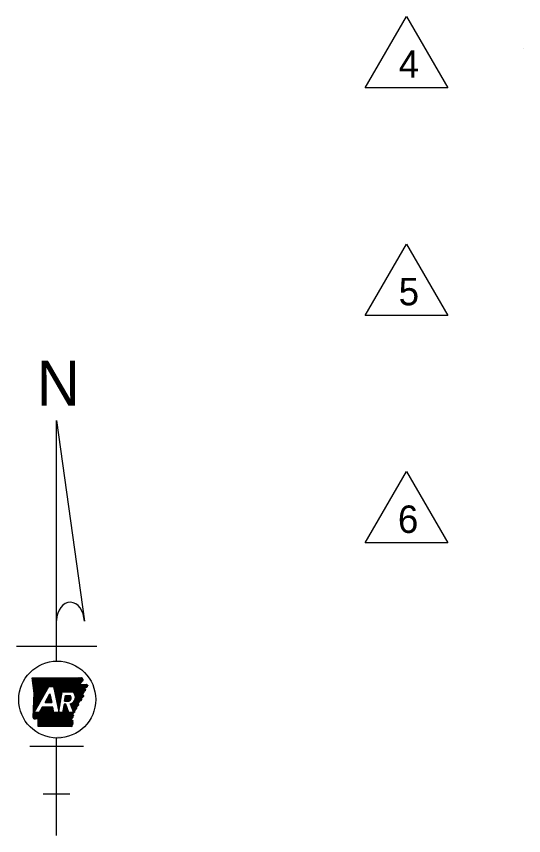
# Model space of a CAD drawing. Extents: x -33639 to 34530, y -17264 to 5867.
# Drawn here: x -7282 to -5621, y -15354 to -12669 of the extents above; entities that cross this region are included whole.
import ezdxf

# ---------------------------------------------------------------- set-up
doc = ezdxf.new("R2010")
doc.units = 0
doc.layers.add('R_Annotation', color=7, linetype='Continuous')
doc.layers.add('S_MISC_BOUNDARY', color=7, linetype='Continuous')

msp = doc.modelspace()

# ---------------------------------------------------------------- linework, layer by layer
at = {"layer": 'R_Annotation'}
for p, q in [((-7150.3, -13993.8), (-7059.3, -14650.9)), ((-7150.3, -14781.8), (-7150.3, -13993.8)), ((-7281.9, -14733), (-7018.7, -14733)), ((-7230.1, -14838.2), (-7229, -14837.1)), ((-7229.7, -14841.3), (-7225.5, -14837.1)), ((-7229.3, -14844.4), (-7222, -14837.1)), ((-7228.9, -14847.5), (-7218.6, -14837.1)), ((-7228.5, -14850.6), (-7215.1, -14837.1)), ((-7228.2, -14853.7), (-7211.6, -14837.1)), ((-7227.8, -14856.8), (-7208.1, -14837.1)), ((-7227.4, -14859.9), (-7204.6, -14837.1)), ((-7227, -14863), (-7201.2, -14837.1)), ((-7226.6, -14866.1), (-7197.7, -14837.1)), ((-7226.2, -14869.2), (-7194.2, -14837.1)), ((-7225.8, -14872.3), (-7190.7, -14837.1)), ((-7225.5, -14875.4), (-7187.2, -14837.1)), ((-7225.1, -14878.5), (-7183.8, -14837.1)), ((-7225, -14913.2), (-7148.9, -14837.1)), ((-7224.8, -14909.6), (-7152.3, -14837.1)), ((-7224.7, -14906), (-7155.8, -14837.1)), ((-7224.7, -14881.6), (-7180.3, -14837.1)), ((-7224.6, -14902.4), (-7159.3, -14837.1)), ((-7224.5, -14898.8), (-7162.8, -14837.1)), ((-7224.4, -14895.2), (-7166.3, -14837.1)), ((-7224.3, -14884.7), (-7176.8, -14837.1)), ((-7224.2, -14891.6), (-7169.8, -14837.1)), ((-7224.1, -14888), (-7173.3, -14837.1)), ((-7173.2, -14864.9), (-7145.4, -14837.1)), ((-7169.8, -14864.9), (-7141.9, -14837.1)), ((-7166.3, -14864.9), (-7138.4, -14837)), ((-7162.8, -14864.9), (-7134.8, -14837)), ((-7160.6, -14866.3), (-7131.3, -14836.9)), ((-7160, -14869.1), (-7127.8, -14836.9)), ((-7159.4, -14872), (-7124.2, -14836.8)), ((-7158.8, -14874.9), (-7120.7, -14836.8)), ((-7158.2, -14877.7), (-7117.1, -14836.7)), ((-7157.6, -14880.6), (-7113.6, -14836.6)), ((-7156.9, -14883.5), (-7110.1, -14836.6)), ((-7156.3, -14886.3), (-7106.5, -14836.5)), ((-7155.7, -14889.2), (-7103, -14836.5)), ((-7155.1, -14892.1), (-7099.4, -14836.4)), ((-7154.5, -14894.9), (-7095.9, -14836.4)), ((-7153.9, -14897.8), (-7092.4, -14836.3)), ((-7153.3, -14900.7), (-7088.8, -14836.2)), ((-7152.6, -14903.5), (-7085.3, -14836.2)), ((-7128.4, -14882.8), (-7081.7, -14836.1)), ((-7125, -14882.8), (-7078.1, -14836)), ((-7121.5, -14882.8), (-7074.6, -14835.9)), ((-7118, -14882.8), (-7071, -14835.8)), ((-7114.5, -14882.8), (-7067.4, -14835.8)), ((-7111, -14882.8), (-7066.7, -14838.5)), ((-7107.5, -14882.8), (-7065, -14840.3)), ((-7104.1, -14882.8), (-7064.5, -14843.3)), ((-7225.1, -14916.8), (-7178.1, -14869.8)), ((-7223.9, -14950.7), (-7175.3, -14864.9)), ((-7175.3, -14864.9), (-7160.9, -14864.9)), ((-7100.6, -14882.8), (-7072.5, -14854.7)), ((-7097.4, -14883.2), (-7073.2, -14858.9)), ((-7095.5, -14884.7), (-7069.5, -14858.7)), ((-7093.8, -14886.5), (-7065.8, -14858.5)), ((-7092.3, -14888.5), (-7062.1, -14858.3)), ((-7091, -14890.7), (-7058.5, -14858.1)), ((-7090, -14893.1), (-7054.8, -14857.9)), ((-7089.2, -14895.8), (-7051.5, -14858.1)), ((-7088.7, -14898.8), (-7049.9, -14860)), ((-7088.7, -14902.3), (-7058.2, -14871.8)), ((-7051.4, -14865), (-7048.2, -14861.8)), ((-7225.4, -14927.6), (-7191.7, -14893.9)), ((-7225.3, -14924), (-7187.2, -14885.8)), ((-7225.2, -14920.4), (-7182.6, -14877.8)), ((-7188.2, -14917.1), (-7172.3, -14889)), ((-7183.9, -14909.4), (-7170.7, -14896.3)), ((-7179.3, -14901.4), (-7171.3, -14893.4)), ((-7174.8, -14893.4), (-7172, -14890.6)), ((-7152, -14906.4), (-7132.3, -14886.7)), ((-7151.4, -14909.3), (-7133, -14890.9)), ((-7150.8, -14912.2), (-7133.7, -14895.1)), ((-7131.6, -14882.8), (-7097.9, -14882.8)), ((-7124.3, -14913.3), (-7105.9, -14894.9)), ((-7123.5, -14909.1), (-7109.4, -14894.9)), ((-7122.8, -14904.9), (-7112.9, -14894.9)), ((-7122.1, -14900.6), (-7116.4, -14894.9)), ((-7121.3, -14896.4), (-7119.9, -14894.9)), ((-7121.1, -14894.9), (-7105.2, -14894.9)), ((-7120.8, -14913.3), (-7104, -14896.5)), ((-7103.8, -14927.8), (-7065.2, -14889.2)), ((-7102.8, -14930.4), (-7064.5, -14892)), ((-7101.9, -14932.9), (-7063.9, -14894.9)), ((-7101, -14935.4), (-7063.2, -14897.7)), ((-7092.4, -14913), (-7065.8, -14886.4)), ((-7089.4, -14906.5), (-7057.8, -14874.9)), ((-7061.7, -14882.2), (-7057.4, -14877.9)), ((-7225.8, -14938.4), (-7205.4, -14918)), ((-7225.7, -14934.8), (-7200.8, -14909.9)), ((-7225.6, -14931.2), (-7196.3, -14901.9)), ((-7188.2, -14917.1), (-7166.3, -14917.1)), ((-7188, -14917.1), (-7170.1, -14899.2)), ((-7184.5, -14917.1), (-7169.5, -14902)), ((-7181.1, -14917.1), (-7168.9, -14904.9)), ((-7177.6, -14917.1), (-7168.3, -14907.8)), ((-7174.1, -14917.1), (-7167.7, -14910.6)), ((-7170.6, -14917.1), (-7167, -14913.5)), ((-7167.1, -14917.1), (-7166.4, -14916.4)), ((-7150.2, -14915), (-7134.5, -14899.3)), ((-7149.6, -14917.9), (-7135.2, -14903.5)), ((-7149, -14920.8), (-7135.9, -14907.7)), ((-7148.3, -14923.6), (-7136.7, -14912)), ((-7147.7, -14926.5), (-7137.4, -14916.2)), ((-7147.1, -14929.4), (-7138.1, -14920.4)), ((-7146.5, -14932.2), (-7138.9, -14924.6)), ((-7127.3, -14930.4), (-7120.3, -14923.4)), ((-7126.5, -14926.2), (-7123.8, -14923.4)), ((-7120.2, -14923.4), (-7126, -14923.4)), ((-7124.3, -14913.3), (-7109.8, -14913.3)), ((-7110.1, -14950.7), (-7120.2, -14923.4)), ((-7117.3, -14913.3), (-7102.8, -14898.8)), ((-7113.8, -14913.3), (-7102.2, -14901.6)), ((-7110.3, -14913.3), (-7102.5, -14905.4)), ((-7105.9, -14922), (-7095.3, -14950.7)), ((-7105.6, -14922.7), (-7104.6, -14921.7)), ((-7104.7, -14925.3), (-7098.1, -14918.6)), ((-7100, -14938), (-7079.1, -14917.1)), ((-7099.1, -14940.5), (-7079.5, -14921)), ((-7098.1, -14943.1), (-7079.9, -14924.8)), ((-7075.1, -14913.1), (-7070.2, -14908.2)), ((-7226.7, -14967.2), (-7210.3, -14950.7)), ((-7226.6, -14963.6), (-7213.8, -14950.7)), ((-7226.5, -14960), (-7217.2, -14950.7)), ((-7226.4, -14956.4), (-7220.7, -14950.7)), ((-7226.3, -14952.8), (-7223.6, -14950.1)), ((-7226.2, -14949.2), (-7219, -14942)), ((-7226, -14945.6), (-7214.5, -14934)), ((-7225.9, -14942), (-7209.9, -14926)), ((-7225.4, -14969.3), (-7188.8, -14932.7)), ((-7207.3, -14950.7), (-7223.9, -14950.7)), ((-7223.3, -14970.8), (-7185.3, -14932.7)), ((-7220.8, -14971.7), (-7181.8, -14932.7)), ((-7216.7, -14971.1), (-7178.3, -14932.7)), ((-7213.2, -14971), (-7174.9, -14932.7)), ((-7210.4, -14971.8), (-7171.4, -14932.7)), ((-7210.3, -14978.6), (-7164.4, -14932.7)), ((-7210.3, -14975.1), (-7167.9, -14932.7)), ((-7210.3, -14982.1), (-7162.6, -14934.4)), ((-7210.3, -14985.6), (-7162, -14937.3)), ((-7210.3, -14989), (-7161.4, -14940.1)), ((-7210.3, -14992.5), (-7160.7, -14943)), ((-7210.2, -14995.9), (-7160.1, -14945.9)), ((-7197.1, -14932.7), (-7207.3, -14950.7)), ((-7206.7, -14995.9), (-7159.5, -14948.7)), ((-7203.3, -14943.8), (-7192.3, -14932.7)), ((-7203.3, -14996), (-7158, -14950.7)), ((-7199.8, -14996), (-7154.6, -14950.7)), ((-7198.8, -14935.7), (-7195.8, -14932.7)), ((-7162.9, -14932.7), (-7197.1, -14932.7)), ((-7196.3, -14996), (-7151.1, -14950.7)), ((-7192.8, -14996), (-7147.6, -14950.7)), ((-7189.3, -14996), (-7144.1, -14950.7)), ((-7185.9, -14996), (-7140.6, -14950.7)), ((-7182.4, -14996), (-7137.1, -14950.7)), ((-7178.9, -14996), (-7133.7, -14950.7)), ((-7175.4, -14996), (-7115.5, -14936.1)), ((-7172, -14996), (-7114.6, -14938.6)), ((-7168.5, -14996), (-7113.7, -14941.2)), ((-7165, -14996), (-7112.7, -14943.7)), ((-7161.5, -14996), (-7111.8, -14946.3)), ((-7130.8, -14950.7), (-7159.1, -14950.7)), ((-7158, -14996), (-7110.8, -14948.8)), ((-7154.6, -14996), (-7109.3, -14950.7)), ((-7151.1, -14996), (-7105.8, -14950.7)), ((-7147.6, -14996), (-7102.3, -14950.7)), ((-7145.9, -14935.1), (-7139.6, -14928.8)), ((-7145.3, -14938), (-7140.3, -14933)), ((-7144.7, -14940.8), (-7141.1, -14937.3)), ((-7144.1, -14996), (-7098.8, -14950.7)), ((-7144, -14943.7), (-7141.8, -14941.5)), ((-7143.4, -14946.6), (-7142.6, -14945.7)), ((-7130.2, -14947.3), (-7116.5, -14933.6)), ((-7129.5, -14943.1), (-7117.4, -14931)), ((-7128.7, -14938.8), (-7118.4, -14928.5)), ((-7128, -14934.6), (-7119.3, -14925.9)), ((-7095.3, -14950.7), (-7110.1, -14950.7)), ((-7097.2, -14945.6), (-7086.5, -14934.9)), ((-7096.3, -14948.2), (-7088, -14939.9)), ((-7140.7, -14996.1), (-7097.7, -14953.1)), ((-7137.2, -14996.1), (-7097.5, -14956.4)), ((-7133.7, -14996.1), (-7097.4, -14959.7)), ((-7130.2, -14996.1), (-7097.2, -14963)), ((-7126.8, -14996.1), (-7102.9, -14972.2)), ((-7123.3, -14996.1), (-7101.8, -14974.6)), ((-7119.8, -14996.1), (-7100.8, -14977.1)), ((-7116.3, -14996.1), (-7099.7, -14979.5)), ((-7112.8, -14996.1), (-7098.6, -14981.9)), ((-7109.4, -14996.1), (-7097.7, -14984.5)), ((-7105.9, -14996.1), (-7099.3, -14989.5)), ((-7102.4, -14996.1), (-7100.9, -14994.6)), ((-7150.3, -15353.6), (-7150.3, -15033.8)), ((-7238, -15061), (-7062.5, -15061)), ((-7194.1, -15216.8), (-7106.4, -15216.8))]:
    msp.add_line(p, q, dxfattribs=at)
for points in [[(-6004.8, -12669.1), (-5869.8, -12903), (-6139.8, -12903)], [(-6004.8, -13415), (-5869.8, -13648.8), (-6139.8, -13648.8)], [(-6004.8, -14160.9), (-5869.8, -14394.7), (-6139.8, -14394.7)]]:
    msp.add_lwpolyline(points, close=True, dxfattribs=at)
for points in [[(-7230.2, -14837.1), (-7182.2, -14837.1), (-7140, -14837.1), (-7090.3, -14836.3), (-7067.2, -14835.7)], [(-7230.2, -14837.1), (-7182.2, -14837.1), (-7140, -14837.1), (-7090.3, -14836.3), (-7067.2, -14835.7)], [(-7224.9, -14911.8), (-7224.1, -14886.5), (-7230.2, -14837.1)], [(-7226.8, -14967.1), (-7224.1, -14886.5), (-7230.2, -14837.1)], [(-7160.9, -14864.9), (-7143, -14948.4), (-7131.6, -14882.8)], [(-7052.1, -14857.8), (-7048, -14862.2), (-7058.3, -14870.7), (-7057.2, -14879.3), (-7066.1, -14885.2), (-7063, -14898.4), (-7069.9, -14904.6), (-7070.5, -14911.4), (-7078.8, -14914.4), (-7080.1, -14927.3), (-7086.1, -14933.7), (-7089, -14943.3), (-7097.7, -14951.3), (-7097.1, -14965.4), (-7103, -14972), (-7097.6, -14984.1), (-7101.4, -14996.1)], [(-7074.3, -14858.9), (-7051.8, -14857.8)], [(-7074.3, -14859), (-7051.8, -14857.8)], [(-7172.3, -14889), (-7166.3, -14917.1)], [(-7124.3, -14913.3), (-7121.1, -14894.9)], [(-7226.7, -14967.1), (-7224.9, -14911.8)], [(-7126, -14923.4), (-7130.8, -14950.7)], [(-7159.1, -14950.7), (-7162.9, -14932.7)], [(-7101.4, -14996.1), (-7210.3, -14995.9), (-7210.3, -14971.9)], [(-7101.4, -14996.1), (-7210.3, -14995.9), (-7210.3, -14971.9)]]:
    msp.add_lwpolyline(points, dxfattribs=at)
for centre, major_axis, ratio, start_param, end_param in [((-7104.8, -14652.3), (-1.9, 63.2), 0.719778, 4.712385, 7.768526), ((-7113.3, -14902.7), (-11.1, 0), 0.999987, 1.887169, 3.90762), ((-7110.4, -14900.7), (-21.8, 0), 0.999987, 1.777838, 4.099264)]:
    msp.add_ellipse(centre, major_axis=major_axis, ratio=ratio, start_param=start_param, end_param=end_param, dxfattribs=at)
msp.add_ellipse((-7148.2, -14907.8), major_axis=(126, 0), ratio=0.999976, dxfattribs=at)
for points in [[(-7067.2, -14835.7), (-7067.1, -14837.1), (-7066.7, -14837.7), (-7066.6, -14839), (-7066.1, -14839.5), (-7065.2, -14840.1), (-7064.5, -14840.9), (-7064.3, -14841.9), (-7064.5, -14843), (-7064.6, -14844.1), (-7064.7, -14845.2), (-7064.9, -14846), (-7065.6, -14846.8), (-7066.3, -14847.3), (-7066.9, -14847.9), (-7067.3, -14848.6), (-7068.1, -14849.3), (-7068.9, -14850.1), (-7069.5, -14850.7), (-7070.1, -14851.6), (-7070.4, -14852.5), (-7071.1, -14853.1), (-7071.6, -14853.7), (-7072.4, -14854.5), (-7072.7, -14855.3), (-7073.4, -14856.2), (-7073.5, -14857.1), (-7074, -14857.8), (-7074, -14858)], [(-7067.2, -14835.7), (-7067.1, -14837.1), (-7066.6, -14837.7), (-7066.6, -14839), (-7066.1, -14839.5), (-7065.2, -14840.1), (-7064.4, -14840.9), (-7064.3, -14841.9), (-7064.5, -14843), (-7064.6, -14844.1), (-7064.7, -14845.1), (-7064.9, -14846.1), (-7065.6, -14846.8), (-7066.3, -14847.3), (-7066.9, -14848), (-7067.3, -14848.6), (-7068.1, -14849.3), (-7068.9, -14850.1), (-7069.5, -14850.7), (-7070.1, -14851.6), (-7070.4, -14852.5), (-7071.1, -14853.1), (-7071.6, -14853.7), (-7072.3, -14854.5), (-7072.7, -14855.3), (-7073.4, -14856.2), (-7073.5, -14857.1), (-7074, -14857.9), (-7074, -14858)], [(-7052.1, -14857.8), (-7051.8, -14857.8), (-7050.8, -14858.9), (-7050.3, -14859.8), (-7049.7, -14860.3), (-7048.9, -14860.5), (-7048.4, -14861.2), (-7048, -14862), (-7048.2, -14862.6), (-7049, -14862.7), (-7050, -14862.8), (-7050.8, -14862.8), (-7051.6, -14863.4), (-7050.9, -14864.2), (-7050, -14864.9), (-7049.8, -14865.7), (-7050.3, -14866.5), (-7051.2, -14866.9), (-7052.1, -14867.3), (-7053, -14868), (-7053.4, -14868.7), (-7054.3, -14869), (-7055.2, -14869.2), (-7056.1, -14869.3), (-7057, -14869.5), (-7057.9, -14870), (-7058.3, -14870.7), (-7058.2, -14871.8), (-7058.2, -14873), (-7057.3, -14873.4), (-7056.4, -14873.4), (-7055.5, -14873.8), (-7055.7, -14874.5), (-7056.3, -14875.3), (-7057, -14876), (-7057.8, -14876.3), (-7058.4, -14876.9), (-7058.2, -14877.6), (-7057.6, -14878), (-7057.1, -14878.7), (-7057.2, -14879.3), (-7057.9, -14879.7), (-7058.7, -14879.5), (-7059.3, -14878.8), (-7059.9, -14878.6), (-7060.5, -14878.3), (-7061.1, -14878.7), (-7061.1, -14879.5), (-7061.4, -14880.5), (-7061.1, -14881.1), (-7060.9, -14882.1), (-7060.9, -14882.8), (-7061.1, -14883.8), (-7061.7, -14884.9), (-7062.2, -14885.2), (-7062.5, -14884.1), (-7062.6, -14883.1), (-7063, -14882.6), (-7063.4, -14882.6), (-7064.1, -14883), (-7064.7, -14883.7), (-7065.6, -14884.5), (-7066.1, -14885.2), (-7065.8, -14886.1), (-7065.2, -14886.3), (-7064.7, -14886.2), (-7064.4, -14885.6), (-7063.9, -14885.5), (-7063.4, -14886.4)], [(-7063.4, -14886.4), (-7063.3, -14887.3), (-7063.8, -14888.2), (-7064, -14889.1), (-7063.9, -14890), (-7064.9, -14890.5), (-7065.7, -14891.1), (-7065.2, -14891.9), (-7064.3, -14892.5), (-7063.4, -14893), (-7062.9, -14893.5), (-7062.7, -14894.7), (-7062.6, -14895.5), (-7062.3, -14896.6), (-7062.2, -14897.3), (-7062.7, -14898.2), (-7063.3, -14898.4), (-7064, -14898.2), (-7064.7, -14898.1), (-7065.4, -14898.7), (-7065.8, -14899.5), (-7066.3, -14900.4), (-7066.6, -14901.1), (-7066.9, -14901.9), (-7067.6, -14902.8), (-7068.4, -14902.9), (-7069.3, -14903.1), (-7069.9, -14903.8), (-7069.8, -14904.9), (-7069.2, -14905.6), (-7068.8, -14906.5), (-7068.6, -14907.4), (-7068.7, -14908.4), (-7069.1, -14909.1), (-7069.6, -14909.6), (-7069.9, -14910.5), (-7070.3, -14911.2), (-7070.6, -14911.5), (-7071.3, -14911.4), (-7072.1, -14911.3), (-7072.8, -14911.3), (-7073.4, -14911.6), (-7074, -14911.4), (-7074.7, -14910.7), (-7075.2, -14910.2), (-7075.8, -14910), (-7076.4, -14910.3), (-7076.5, -14911.3), (-7076.2, -14912.3), (-7076, -14913.7), (-7076.2, -14914.5), (-7076.3, -14915.9)], [(-7076.3, -14915.9), (-7077.4, -14916.6), (-7077.8, -14917.5), (-7080.5, -14917.2), (-7080.4, -14918.2), (-7081.3, -14918.7), (-7082.2, -14919.3), (-7081.7, -14920), (-7080.8, -14920.6), (-7079.9, -14921.1), (-7079.4, -14921.6), (-7079.2, -14922.9), (-7079.1, -14923.6), (-7078.8, -14924.7), (-7078.6, -14925.4), (-7079.2, -14926.3), (-7079.8, -14926.5), (-7080.5, -14926.3), (-7081.2, -14926.2), (-7081.8, -14926.8), (-7082.3, -14927.7), (-7082.7, -14928.5), (-7083.1, -14929.2), (-7083.4, -14930), (-7084, -14930.9), (-7084.8, -14931), (-7085.8, -14931.3), (-7086.4, -14931.9), (-7086.3, -14933), (-7085.7, -14933.7), (-7085.3, -14934.7), (-7085, -14935.5), (-7085.2, -14936.5), (-7085.6, -14937.2), (-7086.1, -14937.7), (-7086.4, -14938.6), (-7086.8, -14939.4), (-7087.1, -14939.6), (-7087.8, -14939.5), (-7088.6, -14939.4), (-7089.2, -14939.4), (-7089.9, -14939.8), (-7090.5, -14939.5), (-7091.2, -14938.8), (-7091.7, -14938.3), (-7092.3, -14938.1), (-7092.9, -14938.4), (-7093, -14939.4), (-7092.7, -14940.4), (-7092.5, -14941.8), (-7092.7, -14942.6), (-7092.8, -14944)], [(-7092.8, -14944), (-7092.9, -14944), (-7093.4, -14944.7), (-7093.1, -14945.8), (-7092, -14946.2), (-7091.4, -14947.2), (-7091.4, -14948.1), (-7091.8, -14949.3), (-7092.3, -14949.9), (-7093.4, -14950.1), (-7094.2, -14950.2), (-7094.3, -14951.6), (-7094.6, -14952.3), (-7095.3, -14952.5), (-7096.2, -14952.1), (-7096.7, -14951.8), (-7097.3, -14951.5), (-7098.2, -14951.1), (-7098.8, -14951.1), (-7098.6, -14952.4), (-7098.6, -14952.5), (-7097.8, -14953.5), (-7097.1, -14954.3), (-7096.8, -14955.2)], [(-7092.8, -14944), (-7092.9, -14944), (-7093.4, -14944.7), (-7093.1, -14945.8), (-7092, -14946.2), (-7091.4, -14947.2), (-7091.4, -14948.1), (-7091.8, -14949.3), (-7092.3, -14949.9), (-7093.4, -14950.1), (-7094.2, -14950.2), (-7094.3, -14951.6), (-7094.6, -14952.3), (-7095.3, -14952.5), (-7096.2, -14952.1), (-7096.7, -14951.8), (-7097.3, -14951.5), (-7098.2, -14951.1), (-7098.8, -14951.1), (-7098.6, -14952.4), (-7098.6, -14952.5), (-7097.8, -14953.5), (-7097.1, -14954.3), (-7096.8, -14955.2)], [(-7210.3, -14971.9), (-7210.2, -14972), (-7210.8, -14971.6), (-7211.5, -14971.2), (-7212.4, -14971.1), (-7213.5, -14971), (-7214.4, -14970.9), (-7215.4, -14970.3), (-7216.4, -14970.9), (-7217.5, -14971.4), (-7218.2, -14970.9), (-7219, -14971.2), (-7219.6, -14971), (-7220.7, -14971.8), (-7221.6, -14971.5), (-7222.4, -14971.7), (-7223.2, -14971.7), (-7223.4, -14970.7), (-7224.3, -14970.5), (-7225, -14970.1), (-7225.5, -14969), (-7225.9, -14968.2), (-7226.8, -14967.1)], [(-7210.3, -14971.9), (-7210.2, -14972), (-7210.8, -14971.6), (-7211.5, -14971.2), (-7212.4, -14971.1), (-7213.5, -14971), (-7214.4, -14970.9), (-7215.4, -14970.3), (-7216.4, -14970.9), (-7217.5, -14971.4), (-7218.2, -14970.8), (-7219, -14971.2), (-7219.6, -14971), (-7220.7, -14971.8), (-7221.7, -14971.5), (-7222.3, -14971.7), (-7223.2, -14971.7), (-7223.4, -14970.6), (-7224.3, -14970.5), (-7225, -14970.1), (-7225.5, -14969.1), (-7225.9, -14968.2), (-7226.7, -14967.1)], [(-7096.8, -14955.2), (-7097.1, -14955.9), (-7097.4, -14957), (-7097.3, -14958), (-7096.9, -14958.9), (-7096.2, -14959.4), (-7095.4, -14960.1), (-7095.5, -14961.1), (-7095.9, -14961.5), (-7097, -14961.2), (-7097.8, -14960.9), (-7098.4, -14961.1), (-7099.3, -14961.5), (-7100, -14961.6), (-7100, -14963.1), (-7099.1, -14964.1), (-7098.3, -14964.1), (-7097.4, -14964.2), (-7097, -14965.2), (-7097.6, -14966.1), (-7098.5, -14966.6), (-7099.6, -14966), (-7100.4, -14965.5), (-7101.2, -14964.9), (-7102.2, -14964.7), (-7102.8, -14964.8), (-7103, -14966), (-7102.6, -14967.2), (-7101.8, -14968), (-7101.1, -14969), (-7101.2, -14969.7), (-7101.7, -14969.9), (-7102.7, -14970.1), (-7103.3, -14970.4), (-7103.4, -14970.6), (-7103.1, -14971.7), (-7102.8, -14972.8), (-7102.8, -14973.6), (-7103.2, -14974.3), (-7103.7, -14975.5), (-7103.6, -14976.3), (-7103.3, -14976.7), (-7102.8, -14976.6), (-7102.2, -14976.2), (-7101.8, -14975.7), (-7101.5, -14975.1), (-7100.9, -14974.6), (-7100.1, -14975), (-7099.9, -14975.9), (-7100.4, -14976.7), (-7101, -14977.1), (-7101.8, -14977.4), (-7102.3, -14978), (-7102.2, -14978.8), (-7101.7, -14979.2), (-7100.6, -14979), (-7099.9, -14978.7), (-7099.5, -14978.3), (-7099, -14977.8), (-7098.7, -14977.3), (-7098.3, -14976.7), (-7097.6, -14976.6), (-7097.3, -14977), (-7097.4, -14978), (-7097.8, -14979), (-7098.4, -14979.8), (-7099, -14980.4), (-7099.8, -14981.6), (-7099.7, -14982.7), (-7099.3, -14983.7), (-7099, -14984.3), (-7098.2, -14984.2), (-7097.4, -14984.1), (-7097, -14984.5), (-7097, -14985.3), (-7097.6, -14986.2), (-7098.2, -14986.9), (-7098.5, -14988), (-7098.3, -14988.7), (-7098.3, -14989.4), (-7098.6, -14990.2), (-7099, -14990.6), (-7100.1, -14990.6), (-7101.3, -14990.4), (-7101.9, -14990.8), (-7101.8, -14991.8), (-7101.1, -14992.5), (-7100.6, -14992.9), (-7099.9, -14993.7), (-7099.6, -14994.4), (-7099.7, -14995), (-7100.2, -14995.5), (-7101.4, -14996.1)], [(-7096.8, -14955.2), (-7097.1, -14955.9), (-7097.4, -14957), (-7097.3, -14958), (-7096.9, -14958.9), (-7096.2, -14959.4), (-7095.4, -14960.1), (-7095.5, -14961.1), (-7095.9, -14961.5), (-7097, -14961.2), (-7097.8, -14960.9), (-7098.4, -14961.1), (-7099.3, -14961.5), (-7100, -14961.6), (-7100, -14963.1), (-7099.1, -14964.1), (-7098.3, -14964.1), (-7097.4, -14964.2), (-7097, -14965.2), (-7097.6, -14966.1), (-7098.5, -14966.6), (-7099.6, -14966), (-7100.4, -14965.5), (-7101.2, -14964.9), (-7102.2, -14964.7), (-7102.8, -14964.8), (-7103, -14966), (-7102.6, -14967.2), (-7101.8, -14968), (-7101.1, -14969), (-7101.2, -14969.7), (-7101.7, -14969.9), (-7102.7, -14970.1), (-7103.3, -14970.4), (-7103.4, -14970.6), (-7103.1, -14971.7), (-7102.8, -14972.8), (-7102.8, -14973.6), (-7103.2, -14974.3), (-7103.7, -14975.5), (-7103.6, -14976.3), (-7103.3, -14976.7), (-7102.8, -14976.6), (-7102.2, -14976.2), (-7101.8, -14975.7), (-7101.5, -14975.1), (-7100.9, -14974.6), (-7100.1, -14975), (-7099.9, -14975.9), (-7100.4, -14976.7), (-7101, -14977.1), (-7101.8, -14977.4), (-7102.3, -14978), (-7102.2, -14978.8), (-7101.7, -14979.2), (-7100.6, -14979), (-7099.9, -14978.7), (-7099.5, -14978.3), (-7099, -14977.8), (-7098.7, -14977.3), (-7098.3, -14976.7), (-7097.6, -14976.6), (-7097.3, -14977), (-7097.4, -14978), (-7097.8, -14979), (-7098.4, -14979.8), (-7099, -14980.4), (-7099.8, -14981.6), (-7099.7, -14982.7), (-7099.3, -14983.7), (-7099, -14984.3), (-7098.2, -14984.2), (-7097.4, -14984.1), (-7097, -14984.5), (-7097, -14985.3), (-7097.6, -14986.2), (-7098.2, -14986.9), (-7098.5, -14988), (-7098.3, -14988.7), (-7098.3, -14989.4), (-7098.6, -14990.2), (-7099, -14990.6), (-7100.1, -14990.6), (-7101.3, -14990.4), (-7101.9, -14990.8), (-7101.8, -14991.8), (-7101.1, -14992.5), (-7100.6, -14992.9), (-7099.9, -14993.7), (-7099.6, -14994.4), (-7099.7, -14995), (-7100.2, -14995.5), (-7101.4, -14996.1)]]:
    msp.add_spline(points, degree=3, dxfattribs=at)
at = {"layer": 'S_MISC_BOUNDARY'}
msp.add_line((-5621.2, -12775.5), (-5621.2, -12775.5), dxfattribs=at)

# ---------------------------------------------------------------- texts
at = {"layer": 'R_Annotation'}
for s, height, p in [('4', 90, (-6030.3, -12870)), ('5', 90, (-6030.3, -13615.9)), ('N', 146.7, (-7215.6, -13944.2)), ('6', 90, (-6032.8, -14361.8)), ('STS 10-03-17', 3.644, (-7160.3, -15032.8))]:
    msp.add_text(s, height=height, dxfattribs=at).set_placement(p)

doc.saveas('drawing.dxf')
